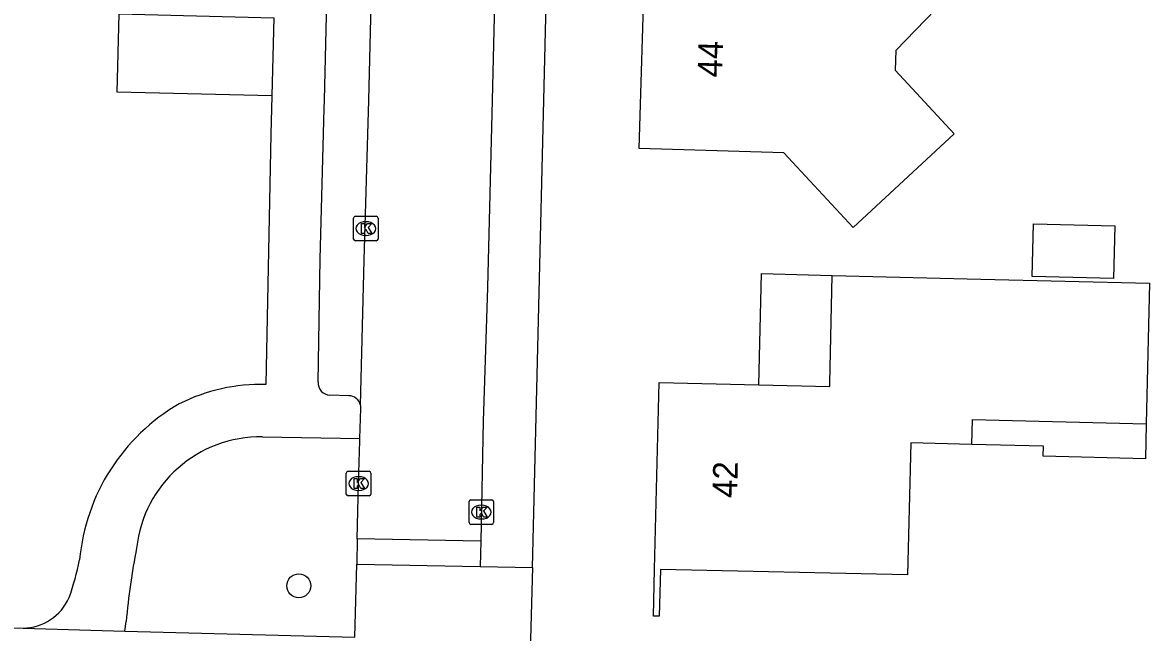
# Model space of a CAD drawing. Extents: x 162082 to 163393, y 388091 to 388632.
# Drawn here: x 162396.48 to 162442.34, y 388478.36 to 388503.16 of the extents above; entities that cross this region are included whole.
import ezdxf

# ---------------------------------------------------------------- set-up
doc = ezdxf.new("R2010")
doc.units = 0
for name, color, linetype in [('IMGEO_Boom', 7, 'Continuous'), ('IMGEO_Erf', 7, 'Continuous'), ('IMGEO_Kolk', 7, 'Continuous'), ('IMGEO_Pand', 7, 'Continuous'), ('IMGEO_Pand_nummerreeks', 7, 'Continuous'), ('IMGEO_Rijbaan_lokaal_open', 7, 'Continuous'), ('IMGEO_Voetpad_open', 7, 'Continuous')]:
    doc.layers.add(name, color=color, linetype=linetype)

msp = doc.modelspace()

# ---------------------------------------------------------------- linework, layer by layer
at = {"layer": 'IMGEO_Boom'}
msp.add_circle((162407.723, 388480.257), 0.489, dxfattribs=at)
at = {"layer": 'IMGEO_Erf'}
for points in [[(162426.439, 388488.429), (162426.549, 388492.95), (162429.432, 388492.88)], [(162442.205, 388486.837), (162442.173, 388485.418), (162438.01, 388485.526), (162438.02, 388485.93), (162435.104, 388486.006)]]:
    msp.add_lwpolyline(points, dxfattribs=at)
at = {"layer": 'IMGEO_Kolk'}
for p, q in [((162409.951, 388494.358), (162409.951, 388495.21)), ((162410.026, 388495.284), (162410.878, 388495.284)), ((162410.439, 388495.064), (162410.464, 388495.064)), ((162410.952, 388495.21), (162410.952, 388494.358)), ((162410.878, 388494.284), (162410.026, 388494.284)), ((162410.462, 388494.504), (162410.437, 388494.504)), ((162409.657, 388483.988), (162409.657, 388484.84)), ((162409.732, 388484.914), (162410.584, 388484.914)), ((162410.145, 388484.694), (162410.17, 388484.694)), ((162410.658, 388484.84), (162410.658, 388483.988)), ((162410.168, 388484.134), (162410.143, 388484.134)), ((162410.584, 388483.914), (162409.732, 388483.914)), ((162414.649, 388482.827), (162414.649, 388483.679)), ((162414.724, 388483.753), (162415.576, 388483.753)), ((162415.65, 388483.679), (162415.65, 388482.827)), ((162415.137, 388483.533), (162415.162, 388483.533)), ((162415.576, 388482.753), (162414.724, 388482.753)), ((162415.16, 388482.973), (162415.135, 388482.973))]:
    msp.add_line(p, q, dxfattribs=at)
for points in [[(162409.951, 388494.358), (162409.951, 388495.21)], [(162410.026, 388495.284), (162410.878, 388495.284)], [(162410.952, 388495.21), (162410.952, 388494.358)], [(162410.272, 388494.984), (162410.395, 388494.984), (162410.395, 388494.833), (162410.525, 388494.984), (162410.689, 388494.984), (162410.543, 388494.833), (162410.696, 388494.584), (162410.544, 388494.584), (162410.459, 388494.748), (162410.395, 388494.681), (162410.395, 388494.584), (162410.272, 388494.584), (162410.272, 388494.984)], [(162410.878, 388494.284), (162410.026, 388494.284)], [(162409.657, 388483.988), (162409.657, 388484.84)], [(162409.732, 388484.914), (162410.584, 388484.914)], [(162409.978, 388484.614), (162410.101, 388484.614), (162410.101, 388484.463), (162410.231, 388484.614), (162410.395, 388484.614), (162410.249, 388484.463), (162410.402, 388484.214), (162410.25, 388484.214), (162410.165, 388484.378), (162410.101, 388484.311), (162410.101, 388484.214), (162409.978, 388484.214), (162409.978, 388484.614)], [(162410.658, 388484.84), (162410.658, 388483.988)], [(162410.584, 388483.914), (162409.732, 388483.914)], [(162414.649, 388482.827), (162414.649, 388483.679)], [(162414.724, 388483.753), (162415.576, 388483.753)], [(162415.65, 388483.679), (162415.65, 388482.827)], [(162414.97, 388483.453), (162415.093, 388483.453), (162415.093, 388483.302), (162415.223, 388483.453), (162415.387, 388483.453), (162415.241, 388483.302), (162415.394, 388483.053), (162415.242, 388483.053), (162415.157, 388483.217), (162415.093, 388483.15), (162415.093, 388483.053), (162414.97, 388483.053), (162414.97, 388483.453)], [(162415.576, 388482.753), (162414.724, 388482.753)]]:
    msp.add_lwpolyline(points, dxfattribs=at)
for centre, start, end in [((162410.028, 388495.208), 91.552, 178.448), ((162410.028, 388495.208), 91.552, 178.448), ((162410.876, 388495.208), 1.552, 88.448), ((162410.876, 388495.208), 1.552, 88.448), ((162410.028, 388494.36), 181.552, 268.448), ((162410.028, 388494.36), 181.552, 268.448), ((162410.876, 388494.36), 271.552, 358.448), ((162410.876, 388494.36), 271.552, 358.448), ((162409.734, 388484.838), 91.552, 178.448), ((162409.734, 388484.838), 91.552, 178.448), ((162410.582, 388484.838), 1.552, 88.448), ((162410.582, 388484.838), 1.552, 88.448), ((162409.734, 388483.99), 181.552, 268.448), ((162409.734, 388483.99), 181.552, 268.448), ((162410.582, 388483.99), 271.552, 358.448), ((162410.582, 388483.99), 271.552, 358.448), ((162414.726, 388483.677), 91.552, 178.448), ((162414.726, 388483.677), 91.552, 178.448), ((162415.574, 388483.677), 1.552, 88.448), ((162415.574, 388483.677), 1.552, 88.448), ((162414.726, 388482.829), 181.552, 268.448), ((162414.726, 388482.829), 181.552, 268.448), ((162415.574, 388482.829), 271.552, 358.448), ((162415.574, 388482.829), 271.552, 358.448)]:
    msp.add_arc(centre, 0.0765, start, end, dxfattribs=at)
for centre, major_axis, ratio, start_param, end_param in [((162410.438, 388494.784), (-0.387, 0.002), 0.722429, 4.712389, 7.853982), ((162410.463, 388494.784), (-0.39, 0.002), 0.717154, 1.570796, 4.712389), ((162410.144, 388484.414), (-0.387, 0.002), 0.722429, 4.712389, 7.853982), ((162410.169, 388484.414), (-0.39, 0.002), 0.717154, 1.570796, 4.712389), ((162415.136, 388483.253), (-0.387, 0.002), 0.722429, 4.712389, 7.853982), ((162415.161, 388483.253), (-0.39, 0.002), 0.717154, 1.570796, 4.712389)]:
    msp.add_ellipse(centre, major_axis=major_axis, ratio=ratio, start_param=start_param, end_param=end_param, dxfattribs=at)
at = {"layer": 'IMGEO_Pand'}
for points in [[(162430.277, 388494.828), (162427.457, 388497.864), (162421.578, 388498.035), (162421.802, 388505.649), (162423.951, 388505.594), (162423.985, 388506.744), (162424.665, 388506.726), (162424.745, 388509.445), (162432.87, 388509.241), (162436.031, 388506.184), (162432.014, 388502.029), (162431.99, 388501.221), (162434.385, 388498.642), (162430.277, 388494.828)], [(162406.62, 388500.18), (162400.34, 388500.33), (162400.42, 388503.52), (162406.71, 388503.36)], [(162406.71, 388503.36), (162406.62, 388500.18)], [(162437.616, 388494.981), (162440.929, 388494.9), (162440.876, 388492.75), (162437.564, 388492.831), (162437.616, 388494.981)], [(162426.439, 388488.429), (162429.326, 388488.357), (162429.325, 388488.49), (162429.432, 388492.88)], [(162429.432, 388492.88), (162435.474, 388492.732), (162442.336, 388492.564), (162442.205, 388486.837)], [(162435.104, 388486.006), (162432.62, 388486.07), (162432.49, 388480.7), (162422.441, 388480.925), (162422.393, 388479.02), (162422.152, 388479.026), (162422.2, 388480.93), (162422.39, 388488.53), (162426.439, 388488.429)], [(162435.104, 388486.006), (162435.13, 388487.021), (162442.205, 388486.837)]]:
    msp.add_lwpolyline(points, dxfattribs=at)
at = {"layer": 'IMGEO_Rijbaan_lokaal_open'}
for points in [[(162416.189, 388524.501), (162415.951, 388514.799), (162415.857, 388511.003), (162415.82, 388509.487), (162415.727, 388505.682), (162415.587, 388500), (162415.4, 388492.385), (162415.281, 388488.605), (162415.229, 388486.958), (162415.125, 388482.073)], [(162410.236, 388487.606), (162410.38, 388493.501), (162410.577, 388500), (162411.028, 388518.934)], [(162410.212, 388486.241), (162410.248, 388487.471)], [(162410.104, 388482.171), (162410.158, 388484.414), (162410.209, 388486.151), (162410.212, 388486.241)], [(162410.104, 388482.171), (162410.079, 388481.141)], [(162415.125, 388482.073), (162410.104, 388482.171)], [(162415.125, 388482.073), (162415.103, 388481.036)], [(162410.079, 388481.141), (162415.103, 388481.036)]]:
    msp.add_lwpolyline(points, dxfattribs=at)
msp.add_arc((162409.789, 388487.498), 0.459, 356.5985, 13.5607, dxfattribs=at)
at = {"layer": 'IMGEO_Voetpad_open'}
for points in [[(162417.228, 388480.994), (162417.689, 388500), (162418.288, 388524.692)], [(162408.512, 388488.541), (162408.599, 388493.534), (162408.757, 388499.663), (162408.765, 388500), (162408.849, 388503.452), (162409.167, 388516.459)], [(162406.62, 388500.18), (162406.587, 388498.618), (162406.382, 388488.442)], [(162409.758, 388487.984), (162408.985, 388488.01)], [(162406.253, 388486.315), (162410.212, 388486.241)], [(162400.65, 388478.41), (162410.008, 388478.167), (162410.079, 388481.141)], [(162415.103, 388481.036), (162417.228, 388480.994)], [(162417.228, 388480.994), (162417.157, 388478.082), (162417.147, 388477.667)], [(162326.67, 388467.741), (162326.772, 388471.823), (162335.557, 388480.119), (162369.201, 388479.245), (162396.51, 388478.538)], [(162396.51, 388478.538), (162400.65, 388478.41)], [(162400.65, 388478.41), (162400.699, 388478.808)]]:
    msp.add_lwpolyline(points, dxfattribs=at)
for centre, radius, start, end in [((162406.179, 388481.082), 7.363, 88.4174, 116.7814), ((162409.007, 388488.506), 0.496, 175.9273, 267.4603), ((162409.759, 388487.494), 0.49, 13.1973, 90.1292), ((162406.949, 388480.575), 8.176, 120.0004, 174.8682), ((162406.175, 388481.234), 5.082, 89.1246, 173.7279), ((162430.502, 388476.08), 29.928, 169.0025, 174.7696), ((162387.745, 388483.582), 11.293, 340.3026, 348.3713), ((162396.482, 388480.606), 2.069, 270.7642, 336.3322)]:
    msp.add_arc(centre, radius, start, end, dxfattribs=at)

# ---------------------------------------------------------------- texts
at = {"layer": 'IMGEO_Pand_nummerreeks'}
for s, rotation, p in [('44', 88.3157, (162424.945, 388500.919)), ('42', 88.5678, (162425.553, 388483.819))]:
    msp.add_text(s, height=1, rotation=rotation, dxfattribs=at).set_placement(p)

doc.saveas('drawing.dxf')
